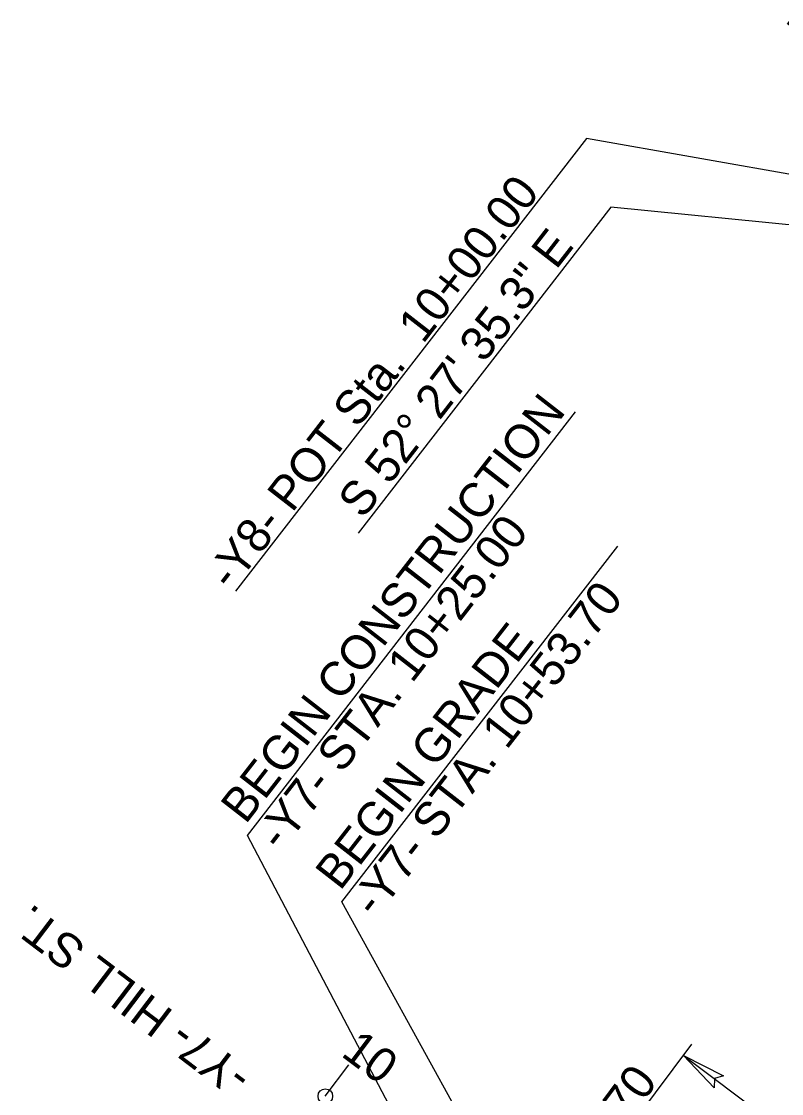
# Model space of a CAD drawing. Extents: x 2010838 to 2015151, y 441905 to 447792.
# Drawn here: x 2014223.3 to 2014378.8, y 445837.2 to 446056.5 of the extents above; entities that cross this region are included whole.
import ezdxf

# ---------------------------------------------------------------- set-up
doc = ezdxf.new("R2010")
doc.units = 0
for name, color, linetype in [('C-EOP 1', 7, 'Continuous'), ('C-Grave Plots', 7, 'Continuous'), ('Cont-2-Lidar', 7, 'Continuous'), ('Default_10ft_LIDAR_Contou', 7, 'Continuous'), ('Default_2FT_LIDAR_Contour', 7, 'Continuous'), ('s-Existing Major', 7, 'Continuous'), ('S-Existing Minor', 7, 'Continuous')]:
    doc.layers.add(name, color=color, linetype=linetype)

msp = doc.modelspace()

# ---------------------------------------------------------------- linework, layer by layer
at = {"layer": 'C-EOP 1'}
msp.add_line((2014285.47, 445836.64), (2014290.26, 445843.05), dxfattribs=at)
at = {"layer": 'Default_10ft_LIDAR_Contou'}
for p, q in [((2014338.92, 446032.54), (2014267.08, 445939.91)), ((2014444.23, 446013.93), (2014338.92, 446032.54)), ((2014343.9, 446018.46), (2014292.21, 445951.81)), ((2014452.32, 446007.72), (2014343.9, 446018.46))]:
    msp.add_line(p, q, dxfattribs=at)
msp.add_circle((2014285.47, 445836.64), 1.5, dxfattribs=at)
at = {"layer": 's-Existing Major'}
msp.add_lwpolyline([(2014365.05, 445838.32), (2014358.77, 445844.96), (2014366.98, 445840.82), (2014365.1, 445840.22)], close=True, dxfattribs=at)
at = {"layer": 'S-Existing Minor'}
for p, q in [((2014269.51, 445889.99), (2014336.69, 445976.62)), ((2014288.87, 445876.37), (2014345.32, 445949.17)), ((2014305.49, 445821.66), (2014269.51, 445889.99)), ((2014328.47, 445804.46), (2014288.87, 445876.37)), ((2014332.56, 445809.93), (2014360.5, 445847.27)), ((2014358.77, 445844.96), (2014438.83, 445785.04))]:
    msp.add_line(p, q, dxfattribs=at)

# ---------------------------------------------------------------- texts
at = {"layer": 'C-Grave Plots'}
for s, rotation, p in [('-Y8- BULLARD ST.', 142.7607, (2014416.08, 446037.27)), ('BEGIN CONSTRUCTION', 52.1339, (2014269.14, 445892.08)), ('-Y7- STA. 10+25.00', 52.1339, (2014276.38, 445886.45)), ('-Y7- STA. 10+53.70', 52.1339, (2014295.74, 445872.84)), ('BEGIN GRADE', 52.1339, (2014288.5, 445878.47)), ('-Y7- HILL ST.', 142.7607, (2014270.82, 445841.56)), ('+53.70', 53.189, (2014336.37, 445816.44))]:
    msp.add_text(s, height=7, rotation=rotation, dxfattribs=at).set_placement(p)
at = {"layer": 'Cont-2-Lidar'}
msp.add_text('S 52%%d 27\' 35.3" E', height=7, rotation=52.2051, dxfattribs=at).set_placement((2014293.14, 445954.51))
at = {"layer": 'Default_10ft_LIDAR_Contou'}
msp.add_text('-Y8- POT Sta.  10+00.00', height=7, rotation=52.2051, dxfattribs=at).set_placement((2014266.24, 445939.79))
at = {"layer": 'Default_2FT_LIDAR_Contour'}
msp.add_text('10', height=7, rotation=323.189, dxfattribs=at).set_placement((2014288.46, 445845))

doc.saveas('drawing.dxf')
